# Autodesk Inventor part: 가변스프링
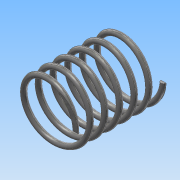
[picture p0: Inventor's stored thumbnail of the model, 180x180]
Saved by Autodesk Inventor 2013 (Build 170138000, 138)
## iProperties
Created: 2016-06
Part Number: 가변스프링
Material: 스테인리스강
Document SubType Name: Modeling
Designer: Administrator
Density: 8.08 g/cm^3
Mass: 85.0412 g
Surface Area: 106.408 cm^2
Volume: 10.5249 cm^3
Author: Administrator
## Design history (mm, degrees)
sketch "스케치1"
  geometry: L1 (0, 0)-(22.5, 0); L2 (22.5, 0)-(22.5, 67.25); L3 (22.5, 67.25)-(0, 67.25); L4 (0, 67.25)-(0, 0); C1 r 2 at (22.5, 0)
  constraints: 8 end point, 2 parallel, 1 centre point, 1 coincident, 1 horizontal, 1 perpendicular
  dimensions: "d1" = 4 diameter of C1; "d3" = 45 diameter of L2 L4; "d4" = 67.25 distance of L3.end L1.start (derived)
feature "코일1" sketch "스케치1" pitch "d5" = 10; turns "d7" = 6; dims "d6" = 67.25 (= d4), "d8" = 0, angle "d9" = 90 deg, angle "d10" = 90 deg, "d11" = 0, "d12" = 0
sketch "스케치2"
  geometry: L1 (0, 30)-(67.25, 30); L2 (67.25, 30)-(67.25, -30); L3 (67.25, -30)-(0, -30); L4 (0, -30)-(0, 30); 4 further points
  constraints: 8 end point, 2 coincident, 2 midpoint, 2 parallel, 1 horizontal, 1 perpendicular
  dimensions: "d13" = 60 distance of L1.end L2.end
extrude "돌출1" sketch "스케치2" stored distance "d16" = 10; taper "d17" = 0 deg
node "솔리드1"
